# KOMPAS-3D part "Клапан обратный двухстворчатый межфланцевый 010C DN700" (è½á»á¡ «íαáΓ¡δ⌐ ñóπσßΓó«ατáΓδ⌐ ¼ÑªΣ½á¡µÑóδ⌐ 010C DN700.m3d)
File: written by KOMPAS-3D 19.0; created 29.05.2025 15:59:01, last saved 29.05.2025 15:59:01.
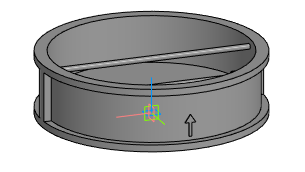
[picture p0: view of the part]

Document properties: Полное имя файла: E:\Dendor Работа Сачек\3D для проекитирвщиков\5.2 Тип 010C, 010C.Y Клапан обратный двухстворчатый межфланцевый\stp_Клапан обратный двухстворчатый межфланцевый 010C\Клапан обратный двухстворчатый межфланцевый 010C DN700.m3d

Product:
- Part/product: Клапан обратный двухстворчатый межфланцевый 010C DN700

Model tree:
1. Операция без истории:1  (labels: Клапан обратный двухстворчатый межфланцевый 010C DN700)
